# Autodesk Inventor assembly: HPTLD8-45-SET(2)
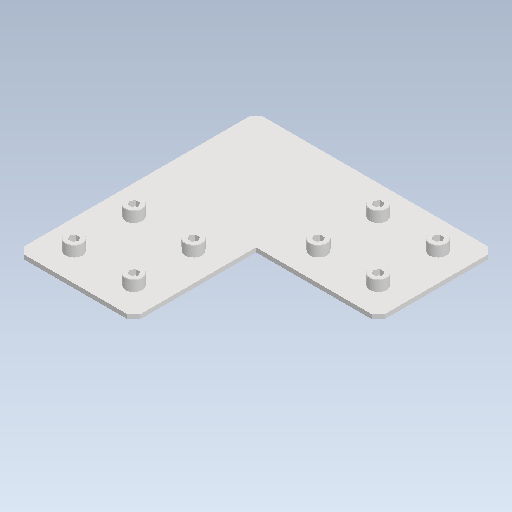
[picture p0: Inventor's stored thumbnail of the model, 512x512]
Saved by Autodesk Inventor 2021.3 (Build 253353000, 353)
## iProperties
Created: 2022-02
Part Number: HPTLD8-45-SET(2)
Document SubType Name: Assembly
Designer: kengo
Author: kengo
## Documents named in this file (4)
- C:\Users\kengo\Documents\S2S_frame\SDC345\frame_misumi_ver12\HPTLD8-45-SET(2).iam
- C:\Users\kengo\Documents\S2S_frame\SDC345\frame_misumi_ver12\HPTLD8-45.ipt
- C:\Users\kengo\Documents\S2S_frame\SDC345\frame_misumi_ver12\HNTT8-8.ipt
- C:\Users\kengo\Documents\S2S_frame\SDC345\frame_misumi_ver12\CBM8-15.ipt
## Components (17 placed, 3 different names)
1. HPTLD8-45
2. HNTT8-8
3. CBM8-15
4. HNTT8-8:1
5. CBM8-15:1
6. HNTT8-8:2
7. CBM8-15:2
8. HNTT8-8:3
9. CBM8-15:3
10. HNTT8-8:4
11. CBM8-15:4
12. HNTT8-8:5
13. CBM8-15:5
14. HNTT8-8:6
15. CBM8-15:6
16. HNTT8-8:7
17. CBM8-15:7
